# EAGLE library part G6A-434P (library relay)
RELAY 4 x switch, 0.3 A/125 V AC, 1 A/30 V DC, Omron
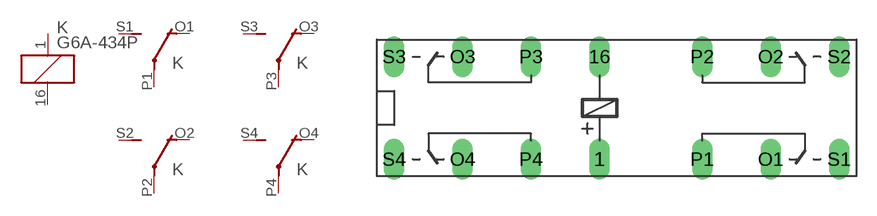
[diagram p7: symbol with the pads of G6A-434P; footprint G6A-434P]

Designator prefix K; gates 1=K 2=U 3=U 4=U 5=U

## G6A-434P (OC_FARNELL: unknown; OC_NEWARK: unknown)  [G6A-434P]
1  1:1  pas
16  1:2  pas
O1  2:O  pas
O2  3:O  pas
O3  4:O  pas
O4  5:O  pas
P1  2:P  pas
P2  3:P  pas
P3  4:P  pas
P4  5:P  pas
S1  2:S  pas
S2  3:S  pas
S3  4:S  pas
S4  5:S  pas

## Footprint G6A-434P (pad centres in mm)
RELAY 4 x switch, 0.3 A/125 V AC, 1 A/30 V DC, Omron
drill 1.016 long: 1 3.81,-3.81; 16 3.81,3.81; O1 16.51,-3.81; O2 16.51,3.81; O3 -6.35,3.81; O4 -6.35,-3.81; P1 11.43,-3.81; P2 11.43,3.81; P3 -1.27,3.81; P4 -1.27,-3.81; S1 21.59,-3.81; S2 21.59,3.81; S3 -11.43,3.81; S4 -11.43,-3.81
